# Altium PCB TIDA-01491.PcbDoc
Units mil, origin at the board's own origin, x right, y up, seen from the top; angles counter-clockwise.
Board outline 866.14 x 1043.31 mil, 4 copper layers (Top Layer, Signal Layer 1, Signal Layer 2, Bottom Layer), stack 61.2 mil thick; 63 components, 22 nets, 130 pads, 71 vias.
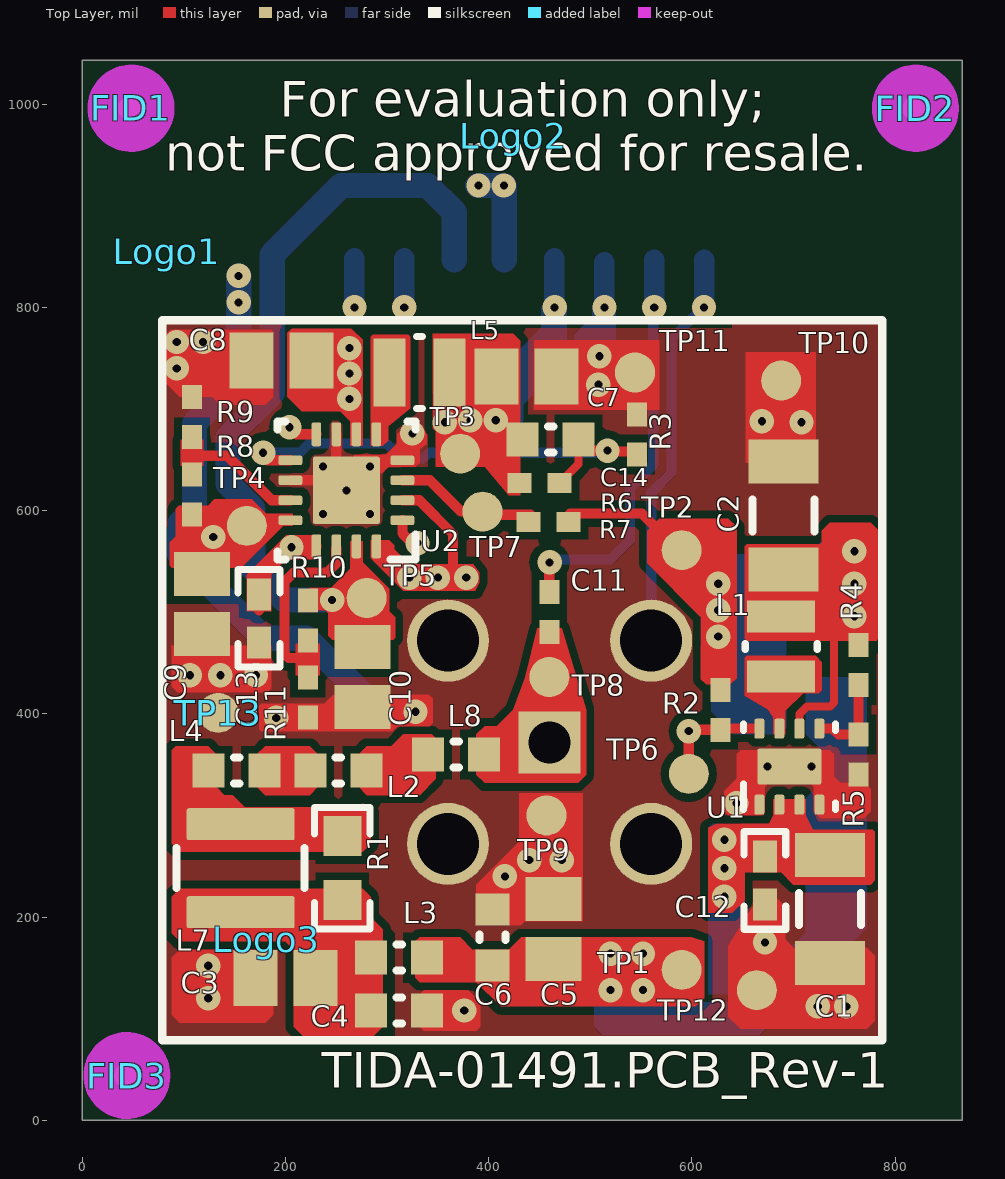
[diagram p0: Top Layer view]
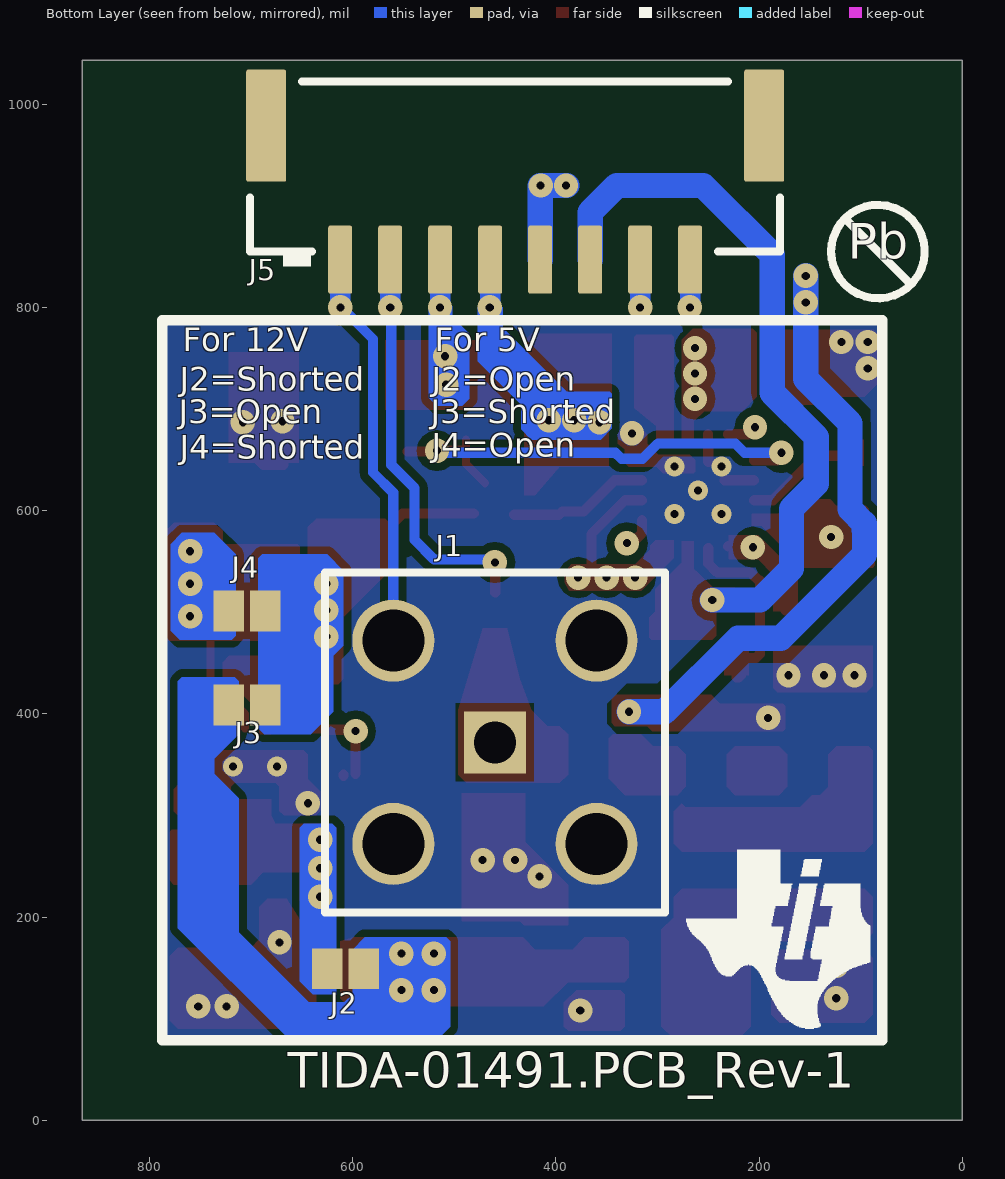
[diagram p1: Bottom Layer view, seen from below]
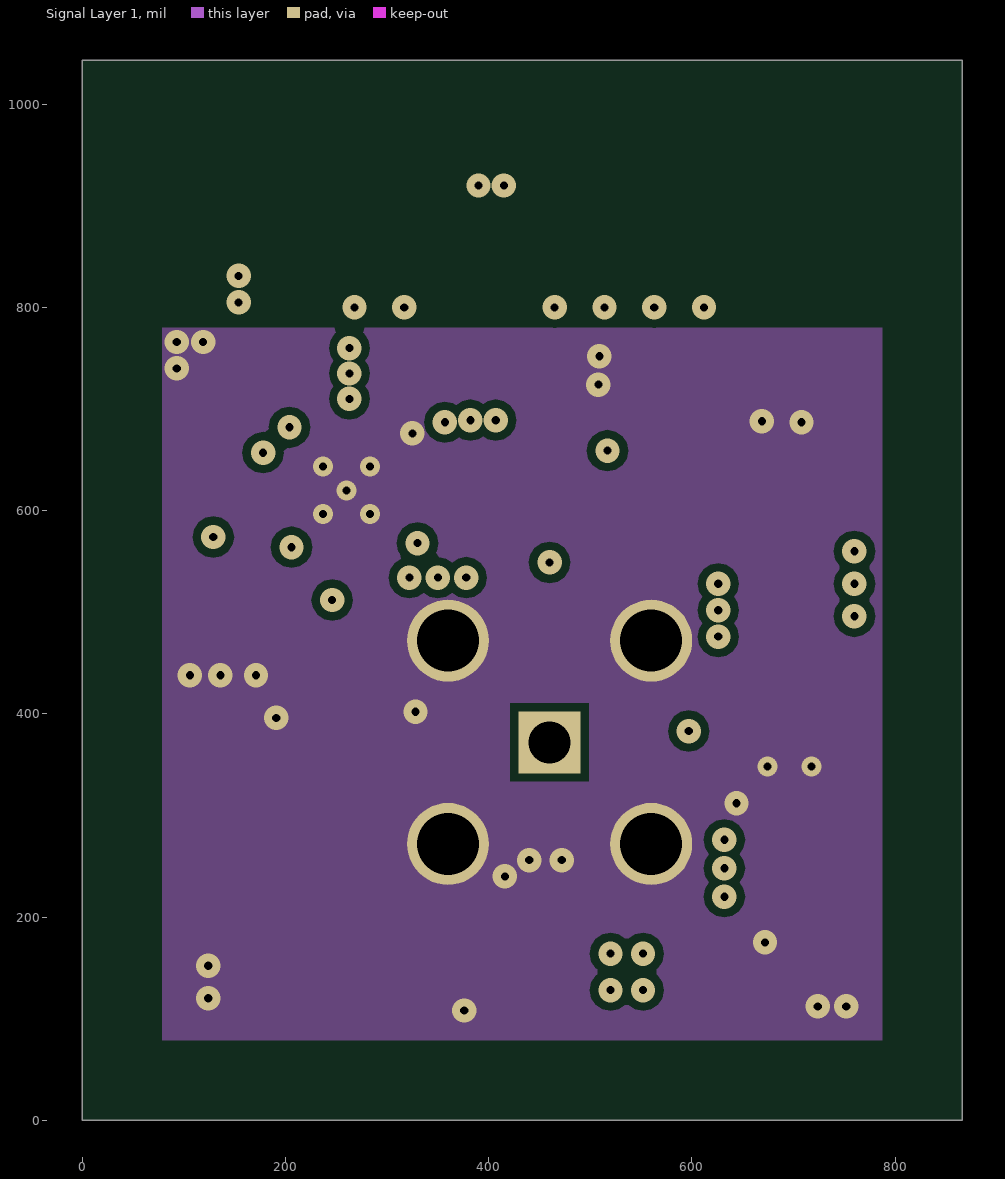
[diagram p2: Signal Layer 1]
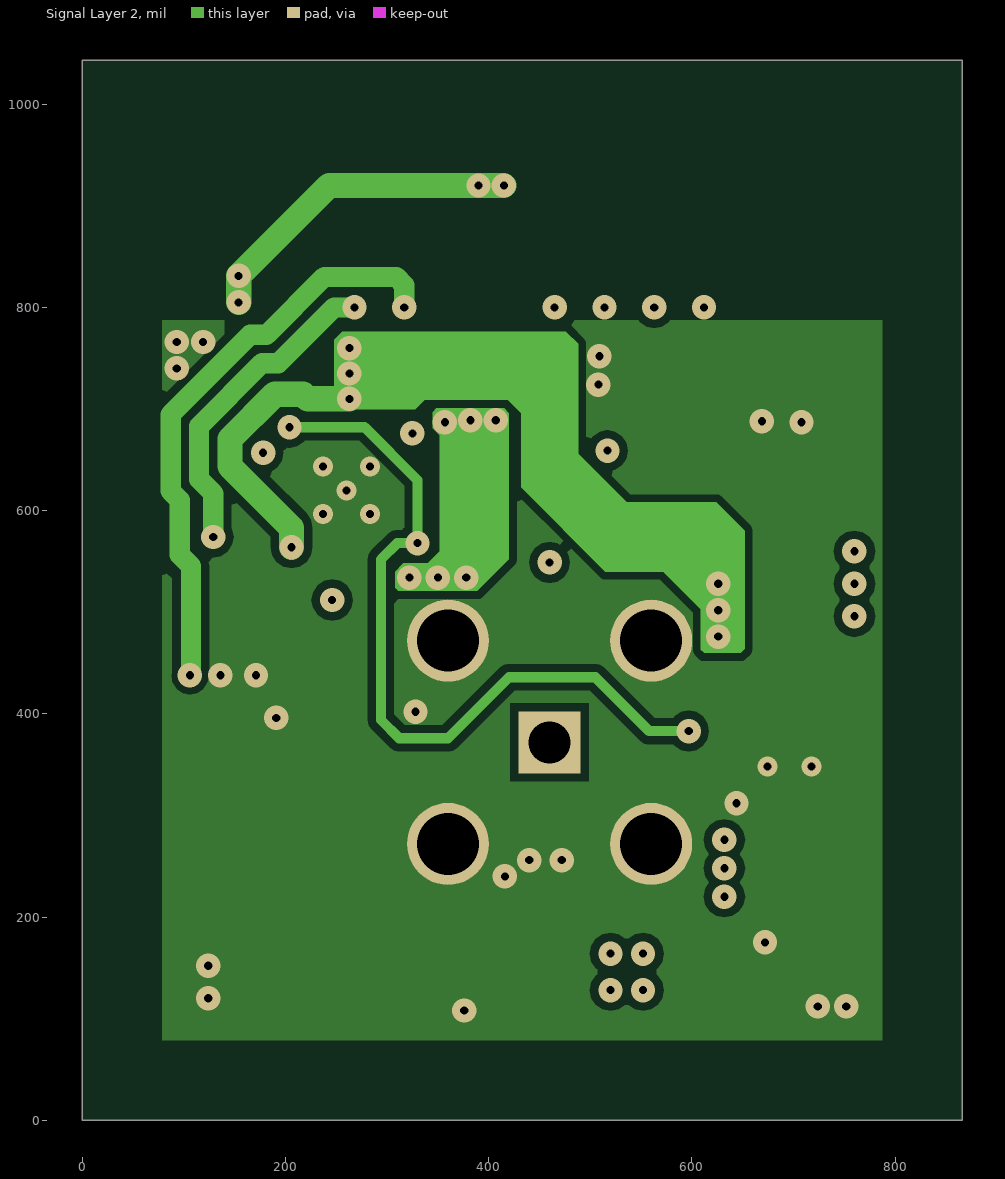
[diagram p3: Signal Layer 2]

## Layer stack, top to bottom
Top Solder: solder mask 0.4, Solder Resist, Dk 3.5
Top Layer: signal copper 1.4
Dielectric 1: prepreg 8, FR-4, Dk 4.2
Signal Layer 1: signal copper 1.4
Dielectric 2: core 8, FR-4, Dk 4.2
Signal Layer 2: signal copper 1.4
Dielectric 3: prepreg 39.6, FR-4, Dk 4.2
Bottom Layer: signal copper 1.4
Bottom Solder: solder mask 0.4, Solder Resist, Dk 3.5

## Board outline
0,0 866.14,0 866.14,1043.31 0,1043.31

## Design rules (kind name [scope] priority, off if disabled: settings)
AcuteAngle [All] p1: minimum=4.50000000000000E+0001 checktracksonly=FALSE
AssemblyTestPointUsage [All] p1: valid=2
BoardOutlineClearance BoardOutlineClearance_MountingHoles [OnCopper and InComponentClass('Mounting Holes')] p1: gap=40 ignorepadtopadclearanceinfootprint=FALSE
BoardOutlineClearance BoardOutlineClearance_Poly [OnCopper and IsPoly] p2: gap=12 ignorepadtopadclearanceinfootprint=FALSE
BoardOutlineClearance [OnCopper and Not InComponentClass('Logo') and not InComponentClass('FiducialMark') and not InRegion(1000,500,4000,800) and not InPoly] p3: gap=9 ignorepadtopadclearanceinfootprint=FALSE
Clearance Clearance_Keepouts [((IsTrack Or IsArc) And Not InPoly) And IsFree and IsKeepOut vs ((IsTrack Or IsArc) And Not InPoly) And IsFree and IsKeepOut] p1: gap=0 ignorepadtopadclearanceinfootprint=FALSE
Clearance Clearance_Poly [InPolygon] p2: gap=8 ignorepadtopadclearanceinfootprint=FALSE
Clearance [All] p3: gap=8 ignorepadtopadclearanceinfootprint=TRUE
ComponentClearance ComponentClearance_1 [InComponentClass('FiducialMark')] p1: gap=0 collisioncheckmode=3 verticalgap=10 showdistances=FALSE
ComponentClearance ComponentClearance_MountingHoles_FiducialMarks [InComponentClass('Mounting Holes') vs InComponentClass('FiducialMark')] p2: gap=0 collisioncheckmode=3 verticalgap=10 showdistances=FALSE
ComponentClearance ComponentClearance_Shunt [InComponentClass('Header') vs InComponentClass('Shunt')] p3: gap=0 collisioncheckmode=3 verticalgap=0 showdistances=FALSE
ComponentClearance ComponentClearance_Logo [InComponentClass('Logo')] p4: gap=25 collisioncheckmode=3 verticalgap=10 showdistances=FALSE
ComponentClearance ComponentClearance_ScrewToNut [(HasFootprint('NY PMS 440 0025 PH')) vs (HasFootprint('Keystone_1902C'))] p5: gap=5 collisioncheckmode=3 verticalgap=10 showdistances=FALSE
ComponentClearance ComponentClearance_MountingHoles [InComponentClass('Mounting Holes')] p6: gap=50 collisioncheckmode=3 verticalgap=100000 showdistances=FALSE
ComponentClearance ComponentClearance_SmallPassives [HasFootprint('0201*') or HasFootprint('0402*') or HasFootprint('0508') or HasFootprint('0603*') or HasFootprint('0612') or HasFootprint('0805*') or HasFootprint('0815*') or HasFootprint('0830*') or HasFootprint('1206*') or HasFootprint('1210*') or HasFootprint('1808*') or HasFootprint('1812*') or HasFootprint('1825*') or HasFootprint('2010*') or HasFootprint('2220*') or HasFootprint('2225*') or HasFootprint('2512*') or HasFootprint('2728*') or HasFootprint('3518*') vs HasFootprint('0201*') or HasFootprint('0402*') or HasFootprint('0508') or HasFootprint('0603*') or HasFootprint('0612') or HasFootprint('0805*') or HasFootprint('0815*') or HasFootprint('0830*') or HasFootprint('1206*') or HasFootprint('1210*') or HasFootprint('1808*') or HasFootprint('1812*') or HasFootprint('1825*') or HasFootprint('2010*') or HasFootprint('2220*') or HasFootprint('2225*') or HasFootprint('2512*') or HasFootprint('2728*') or HasFootprint('3518*')] p7: gap=12 collisioncheckmode=3 verticalgap=10 showdistances=FALSE
ComponentClearance ComponentClearance_THtoSMT [IsThruComponent vs IsSMTComponent] p8: gap=16 collisioncheckmode=3 verticalgap=30 showdistances=FALSE
ComponentClearance ComponentClearance_THtoTH [IsThruComponent vs IsThruComponent] p9: gap=16 collisioncheckmode=3 verticalgap=30 showdistances=FALSE
ComponentClearance [All] p10: gap=12 collisioncheckmode=3 verticalgap=10 showdistances=FALSE
DiffPairsRouting [All] p1: maxlimit=100 minlimit=10 mostfreqgap=10 toplayer_minwidth=15 toplayer_maxwidth=15 toplayer_prefwidth=15 midlayer1_minwidth=15 midlayer1_maxwidth=15 midlayer1_prefwidth=15 midlayer2_minwidth=15 midlayer2_maxwidth=15 midlayer2_prefwidth=15 bottomlayer_minwidth=15 bottomlayer_maxwidth=15 bottomlayer_prefwidth=15 maxuncoupledlength=1000
FabricationTestPointUsage TestPointUsage [All] p1: valid=2 allowmultiple=FALSE
FabricationTestpoint Testpoint [All] p1: side=3 testpointundercomponent=TRUE minsize=40 maxsize=100 preferedsize=60 minholesize=0 maxholesize=40 preferedholesize=32 testpointgrid=1 allowsidetop=TRUE allowsidebottom=TRUE usegrid=TRUE gridtolerance=0.01
FanoutControl Fanout_LCC [IsLCC] p1: bgadir=Out bgaviamode=Centered fanoutstyle=Auto fanoutdirection=Alternating viagrid=1 // Fanout_LCC (Default Rule)
FanoutControl Fanout_BGA [IsBGA] p2: bgadir=Out bgaviamode=Centered fanoutstyle=Auto fanoutdirection=Alternating viagrid=1 // Fanout_BGA (Default Rule)
FanoutControl Fanout_Default [All] p4: bgadir=Out bgaviamode=Centered fanoutstyle=Auto fanoutdirection=Alternating viagrid=1 // Fanout_Default (Default Rule)
FanoutControl Fanout_Small [(CompPinCount < 5)] p5: bgadir=Out bgaviamode=Centered fanoutstyle=Auto fanoutdirection=OutThenIn viagrid=1 // Fanout_Small (Default Rule)
HoleSize [All] p1: absolutevalues=TRUE maxlimit=251 minlimit=7.87 maxpercent=80.000 minpercent=20.000
MinimumAnnularRing MinimumAnnularRing_ThermalPadVias [IsVia and InAnyComponent] p1: minimumring=5.91
MinimumAnnularRing [All] p2: minimumring=8
MinimumSolderMaskSliver MinimumSolderMaskSliver_Logo [InComponentClass('Logo') vs InComponentClass('Logo')] p1: minsoldermaskwidth=0.7
MinimumSolderMaskSliver [All] p2: minsoldermaskwidth=3
PlaneClearance [All] p1: clearance=8
PlaneConnect [All] p1: planeconnectstyle=Direct reliefexpansion=10 reliefentries=4 reliefconductorwidth=10 reliefairgap=10
PolygonConnect [All] p1: connectstyle=Direct reliefconductorwidth=10 reliefentries=4 polygonreliefangle="90 Angle" airgapwidth=10
RoutingVias ThermalPadVias [IsVia and InAnyComponent] p1: holewidth=8 width=24 viastyle="Through Hole" minholewidth=6 minwidth=16 maxholewidth=18 maxwidth=30
RoutingVias [All] p2: holewidth=8 width=16 viastyle="Through Hole" minholewidth=5 minwidth=10 maxholewidth=12 maxwidth=30
SilkToBoardRegionClearance [Not ((IsComment or IsDesignator) And (Hide <> 'False')) and not InRegion(1000,500,4000,800)] p1:
SilkToSilkClearance SilkToSilkClearance_Pb-FreeLogo [(HasFootprint('Pb-Free_Overlay_Medium') OR HasFootprint('Pb-Free_Overlay_Small')) vs (HasFootprint('Pb-Free_Overlay_Medium') OR HasFootprint('Pb-Free_Overlay_Small'))] p1: silktosilkclearance=0
SilkToSilkClearance [All] p2: silktosilkclearance=1
SilkToSolderMaskClearance SilkToComponentPadClearance [(IsPad or IsFill or IsRegion) and InAnycomponent] p1: minsilkscreentomaskgap=1 clearancetoexposedcopper=TRUE
SilkToSolderMaskClearance "Silk to Solder Mask Opening" [All] p2: minsilkscreentomaskgap=4 clearancetoexposedcopper=FALSE
SolderMaskExpansion [All] p1: expansion=1.97
Width [All] p1: maxlimit=100 minlimit=6 preferedwidth=8 checkconnectedcopper=TRUE
14 further rules are at their usual default settings.

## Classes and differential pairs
component class Label: LBL1
component class AssemblyNote: ZZ1 ZZ2 ZZ3 ZZ4
component class FiducialMark: FID1 FID2 FID3
component class EVM_Hardware: FID1 FID2 FID3 LBL1 Logo1 Logo2 Logo3 ZZ1 ZZ2 ZZ3 ZZ4
component class TIDA-01491: C1 C2 C3 C4 C5 C6 C7 C8 C9 C10 C11 C12 C13 C14 J1 J2 J3 J4 J5 L1 L2 L3 L4 L5 L7 L8 R1 R2 R3 R4 R5 R6 R7 R8 R9 R10 R11 TP1 TP2 TP3 TP4 TP5 TP6 TP7 TP8 TP9 TP10 TP11 TP12 TP13 U1 U2
component class Logo: Logo3

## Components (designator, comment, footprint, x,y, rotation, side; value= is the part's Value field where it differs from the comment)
C1 "GCM31CC71E106KA03L" 1206_190L 736,208 r270 top value=10uF
C2 "GCM31CR70J226KE23L" 1206_180L 690,595.15 r90 top value=22uF
C3 "GCM21BC71E475KE36L" 0805L 200,140 r180 top value=4.7uF
C4 "CGA3E2X7R1E104K080AA" 0603L 312,108 r0 top value=0.1uF
C5 "GCM21BC71E475KE36L" 0805L 464,188 r90 top value=4.7uF
C6 "CGA3E2X7R1E104K080AA" 0603L 404,180 r90 top value=0.1uF
C7 "GCM21BR70J106KE22L" 0805L 437.53,732 r0 top value=10uF
C8 "GCM21BR70J106KE22L" 0805L 196,748 r180 top value=10uF
C9 "GCM21BR70J106KE22L" 0805L 118,508 r270 top value=10uF
C10 "GCM21BR70J106KE22L" 0805L 276,436 r270 top value=10uF
C11 "CGA2B1X7R1E333K050BC" 0402L 459.68,500.01 r270 top value=0.033uF
C12 "CGA2B3X7R1H103K050BB" 0402 672,236 r270 top value=0.01uF
C13 "CGA2B3X7R1H103K050BB" 0402 174,494 r270 top value=0.01uF
C14 "GCM1885C1H680JA16D" 0603L 461,670 r0 top value=68pF
FID1 "Fiducial" Fiducial6.4-20 48,996 r0 top
FID2 "Fiducial" Fiducial6.4-20 820,996 r0 top
FID3 "Fiducial" Fiducial6.4-20 44,44 r0 top
J1 "59S10H-40ML5-Z" Rosenberger_59S10H-40ML5-Z 460,372 r270 bottom
J2 "JMP-36-30X40SMT" JMP-36-30X40SMT 607,149 r0 bottom
J3 "JMP-36-30X40SMT" JMP-36-30X40SMT 704,408.69 r180 bottom
J4 "JMP-36-30X40SMT" JMP-36-30X40SMT 704,501.26 r0 bottom
J5 "BM08B-GHS-TBT(LF)(SN)(N)" JST_BM08B-GHS-TBT 439.97,938.54 r180 bottom
L1 "SRN2010TA-2R2M" SRN2010TA 688,466.26 r90 top value=2.2uH
L2 "BLM18HE152SN1D" 0603L 252,344 r180 top value="1500 ohm"
L3 "BLM18KG601SN1D" 0603L 312,160 r0 top value="600 ohm"
L4 "BLM18HE152SN1D" 0603L 152,344 r180 top value="1500 ohm"
L5 "SRN2010TA-2R2M" SRN2010TA 332,736 r0 top value=2.2uH
L7 "LQH3NPZ100MJRL" LQH3NPZ_JR 156,248 r270 top value=10uH
L8 "BLM18HE152SN1D" 0603L 368,360 r180 top value="1500 ohm"
LBL1 "Size: 0.65\" x 0.20 \"" Label_650x200 976,2173 r0 top
Logo1 "Pb-Free Symbol" Pb-Free_Overlay_Small 83,855 r180 top
Logo2 "FCC disclaimer" FCC_disclaimer_stacked 424,969 r0 top
Logo3 "Texas Instruments" TI_Symbol_Overlay_Small 181,178 r180 top
R1 "ERA-3AEB4121V" 0603 256,248 r270 top value=4.12k
R2 "CRCW040211K0JNED" 0402L 628,404 r90 top value=11k
R3 "ERJ-2RKF1503X" 0402L 546,675 r270 top value=150k
R4 "ERJ-2RKF4703X" 0402L 764,448 r90 top value=470k
R5 "ERJ-2RKF1503X" 0402L 764,360 r90 top value=150k
R6 "CRCW0402300KFKED" 0402L 450,627 r180 top value=300k
R7 "ERJ-2RKF4703X" 0402L 459,589 r0 top value=470k
R8 "ERJ-2RKF6983X" 0402L 108,616 r270 top value=698k
R9 "ERJ-2RKF1503X" 0402L 108,692 r270 top value=150k
R10 "ERJ-2RKF2103X" 0402L 222,492 r90 top value=210k
R11 "ERJ-2RKF1503X" 0402L 222,416 r90 top value=150k
TP1 "TP_SM_1MM" TP_SM_1MM 590,148 r180 top
TP2 "TP_SM_1MM" TP_SM_1MM 590,561 r270 top
TP3 "TP_SM_1MM" TP_SM_1MM 372,656 r0 top
TP4 "TP_SM_1MM" TP_SM_1MM 162,585 r0 top
TP5 "TP_SM_1MM" TP_SM_1MM 280,514 r0 top
TP6 "TP_SM_1MM" TP_SM_1MM 597,341 r90 top
TP7 "TP_SM_1MM" TP_SM_1MM 394,599 r90 top
TP8 "TP_SM_1MM" TP_SM_1MM 459.68,436.24 r90 top
TP9 "TP_SM_1MM" TP_SM_1MM 457,300 r90 top
TP10 "TP_SM_1MM" TP_SM_1MM 688,728 r90 top
TP11 "TP_SM_1MM" TP_SM_1MM 544,736 r90 top
TP12 "TP_SM_1MM" TP_SM_1MM 664,128 r90 top
TP13 "TP_SM_1MM" TP_SM_1MM 134,401 r90 top
U1 "TPS62160QDSGRQ1" DSG0008A 696,348 r90 top
U2 "TPS65000TRTERQ1" RTE0016C 260,620 r180 top
ZZ1 "This Assembly Note is for PCB labels only" AssemblyNoteLabel 185,3938 r0 top
ZZ2 "This Assembly Note will show in the PcbDoc and associated outputs" AssemblyNote 185,3829.11 r0 top
ZZ3 "This Assembly Note will show in the PcbDoc and associated outputs" AssemblyNote 185,3740.56 r0 top
ZZ4 "This Assembly Note will show in the PcbDoc and associated outputs" AssemblyNote 185,3652 r0 top

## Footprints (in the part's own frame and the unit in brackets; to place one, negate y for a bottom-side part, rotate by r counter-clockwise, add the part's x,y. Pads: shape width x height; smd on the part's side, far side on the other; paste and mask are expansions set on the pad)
0402 [mm] "0402 from SM-752 data"
  rect 0.8x0.6 smd: 1(-0.6,0) 2(0.6,0)
  silkscreen extent -1.22,-0.52 1.22,0.52, body extent -0.55,-0.3 0.55,0.3, height 0.6
0402L [mm] "0402 from SM-752 data"
  rect 0.6x0.5 smd: 1(-0.5,0) 2(0.5,0)
  body extent -0.55,-0.3 0.55,0.3, height 0.6
0603 [mm] "0603 from SM-752 data"
  rect 1x0.95 smd: 1(-0.8,0) 2(0.8,0)
  silkscreen extent -1.52,-0.69 1.52,0.69, body extent -0.87,-0.47 0.87,0.47, height 1
0603L [mm] "0603 from SM-752 data"
  rect 0.8x0.85 smd: 1(-0.7,0) 2(0.7,0)
  silkscreen extent -0.07,-0.33 0.07,0.33, body extent -0.87,-0.47 0.87,0.47, height 1
0805L [mm] "0805 from SM-752 data"
  rect 1.1x1.4 smd: 1(-0.75,0) 2(0.75,0)
  body extent -1.1,-0.72 1.1,0.72, height 1.45
1206_180L [mm] "1206_180"
  rect 1.1x1.75 smd: 1(-1.35,0) 2(1.35,0)
  silkscreen extent -0.4,-0.77 0.4,0.77, body extent -1.75,-0.95 1.75,0.95, height 1.8
1206_190L [mm] "1206_190"
  rect 1.1x1.75 smd: 1(-1.35,0) 2(1.35,0)
  silkscreen extent -0.4,-0.77 0.4,0.77, body extent -1.75,-0.95 1.75,0.95, height 1.9
AssemblyNote [mil] "Assembly Note"
AssemblyNoteLabel [mil] "Assembly Note for PCB Labels"
DSG0008A [mm] "SON, 8-Leads, Body 2x2mm, Pitch 0.5mm, Thermal Pad 1.6x0.9mm, TI Recommended"
  rrect40% 0.5x0.25 smd: 1(-0.95,0.75) 2(-0.95,0.25) 3(-0.95,-0.25) 4(-0.95,-0.75) 5(0.95,-0.75) 6(0.95,-0.25) 7(0.95,0.25) 8(0.95,0.75)
  rrect14% 0.9x0.7 on Top Paste: 9(0,0.45) 9(0,-0.45)
  rrect11% 0.9x1.6 smd paste-0.45: 9(0,0)
  silkscreen extent -1.07,-1.15 1.07,1.15, body extent -1,-1 1,1, height 0.77
FCC_disclaimer_stacked [mil]
Fiducial6.4-20 [mil]
  round 25 smd mask+26.87: 1(0,0)
  Top Layer keep-out circle w46.37: c0,0 r19.68
JMP-36-30X40SMT [mil] "from PADS library"
  rect 30x40 smd mask+3: 1(-18,0) 2(18,0)
JST_BM08B-GHS-TBT [mm] "Header(shrouded), 1.25mm, 8x1, TH"
  rrect17% 0.6x1.7 smd: 1(-4.375,-2.325) 2(-3.125,-2.325) 3(-1.875,-2.325) 4(-0.625,-2.325) 5(0.625,-2.325) 6(1.875,-2.325) 7(3.125,-2.325) 8(4.375,-2.325)
  rrect10% 1x2.8 smd: MP1(-6.225,1.025) MP2(6.225,1.025)
  silkscreen extent -6.63,-2.5 6.63,2.12, body extent -6.63,-2.83 6.62,2.12, height 4.2
Label_650x200 [mil] "Thermal Transfer Label"
  silkscreen extent -325,-100 325,100, body extent -325,-100 325,100, height 1
LQH3NPZ_JR [mm] "SMD, 2-Leads, Body 3x3mm"
  rrect12% 0.8x2.7 smd: 1(-1.1,0) 2(1.1,0)
  silkscreen extent -0.5,-1.6 0.5,1.6, body extent -1.6,-1.6 1.6,1.6, height 1.2
Pb-Free_Overlay_Small [mil]
Rosenberger_59S10H-40ML5-Z [mm] "Connector, HF, TH"
  rect 1.55x1.55 hole 1.05: 1(0,0)
  round 2.05 hole 1.55: 2(-2.54,2.54) 3(2.54,2.54) 4(2.54,-2.54) 5(-2.54,-2.54)
  silkscreen extent -4.25,-4.25 4.25,4.25, body extent -4.25,-5.75 4.25,4.25, height 12.45
RTE0016C [mm] "Texas Insturments"
  rrect42% 0.6x0.24 smd: 1(-1.4,0.75) 2(-1.4,0.25) 3(-1.4,-0.25) 4(-1.4,-0.75) 9(1.4,-0.75) 10(1.4,-0.25) 11(1.4,0.25) 12(1.4,0.75)
  rrect42% 0.24x0.6 smd: 5(-0.75,-1.4) 6(-0.25,-1.4) 7(0.25,-1.4) 8(0.75,-1.4) 13(0.75,1.4) 14(0.25,1.4) 15(-0.25,1.4) 16(-0.75,1.4)
  rrect6% 1.55x1.55 on Top Paste: 17(0,0)
  rrect6% 1.68x1.68 smd paste-0.85: 17(0,0)
  silkscreen extent -1.72,-1.73 1.72,1.73, body extent -1.57,-1.57 1.58,1.58, height 0.81
SRN2010TA [mm] "SMD, 2-Leads, Body 2.0x1.6mm"
  rect 0.8x1.7 smd: 1(-0.75,0) 2(0.75,0)
  silkscreen extent -0.08,-0.9 0.08,0.9, body extent -1,-0.8 1,0.8, height 0.95
TI_Symbol_Overlay_Small [mil]
TP_SM_1MM [mm] "1mm Test Point, SMT"
  round 1 smd paste-0.5: 1(0,0)

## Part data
C1: library part CMP-0008807-2, "CAP, CERM, 10 uF, 25 V, +/- 10%, X7S, AEC-Q200 Grade 1, 1206_190", Cap_Case=1206, Manufacturer=MuRata, Supplier Part Number 1=490-12661-1-ND, TempCo=X7S, Tolerance_%=10%, Value1=Unknown, Value2=25V, ValueDisplayed=10uF
C2: "CAP, CERM, 22 µF, 6.3 V,+/- 10%, X7R, AEC-Q200 Grade 1, 1206", Cap_Case=1206, Manufacturer=MuRata, Supplier Part Number 1=490-4843-1-ND, TempCo=X7R, Tolerance_%=10, Value2=6.3V, ValueDisplayed=22µF
C3 C5: "CAP, CERM, 4.7 µF, 25 V,+/- 10%, X7S, AEC-Q200 Grade 1, 0805", Cap_Case=0805, Manufacturer=MuRata, Supplier Part Number 1=81-GCM21BC71E475KE6L, TempCo=X7S, Tolerance_%=10, Value2=25V, ValueDisplayed=4.7µF
C4 C6: "CAP, CERM, 0.1 µF, 25 V,+/- 10%, X7R, AEC-Q200 Grade 1, 0603", Cap_Case=0603, Manufacturer=TDK, Supplier Part Number 1=445-5667-1-ND, TempCo=X7R, Tolerance_%=10, Value2=25V, ValueDisplayed=0.1µF
C7 C8 C9 C10: "CAP, CERM, 10 µF, 6.3 V,+/- 10%, X7R, AEC-Q200 Grade 1, 0805", Cap_Case=0805, Manufacturer=MuRata, Supplier Part Number 1=490-5319-1-ND, TempCo=X7R, Tolerance_%=10, Value2=6.3V, ValueDisplayed=10µF
C11: library part CMP-0006306-2, "CAP, CERM, 0.033 uF, 25 V, +/- 10%, X7R, AEC-Q200 Grade 1, 0402", Cap_Case=0402, Manufacturer=TDK, Supplier Part Number 1=445-12247-1-ND, TempCo=X7R, Tolerance_%=10%, Value1=Unknown, Value2=25V, ValueDisplayed=0.033uF
C12 C13: library part CMP-0006324-2, "CAP, CERM, 0.01 uF, 50 V, +/- 10%, X7R, AEC-Q200 Grade 1, 0402", Cap_Case=0402, Manufacturer=TDK, Supplier Part Number 1=445-6893-1-ND, TempCo=X7R, Tolerance_%=10%, Value1="0.333065 ohm", Value2=50V, ValueDisplayed=0.01uF
C14: library part CMP-0007129-4, "CAP, CERM, 68 pF, 50 V, +/- 5%, C0G/NP0, AEC-Q200 Grade 1, 0603", Cap_Case=0603, Manufacturer=MuRata, Supplier Part Number 1=490-4961-1-ND, TempCo=C0G/NP0, Tolerance_%=5%, Value1=Unknown, Value2=50V, ValueDisplayed=68pF
FID1 FID2 FID3: "Fiducial mark.  There is nothing to buy or mount.", Manufacturer=N/A
J1: library part CMP-0075127-1, "Connector, HF, 50 Ohm, TH", Color=Waterblue, Manufacturer=Rosenberger
J2 J3 J4: library part CMP-0003883-1, "Jumper, SMT", Manufacturer=Any
J5: library part CMP-0078455-1, "Header(shrouded), 1.25mm, 8x1, Tin, TH", Color=Natural, Current_A=1A, Manufacturer="JST Manufacturing", Supplier Part Number 1=455-1584-1-ND, Voltage_V=50V
L1 L5: library part CMP-0056730-1, "Inductor, Shielded, Ferrite, 2.2 uH, 1.2 A, 0.174 ohm, AEC-Q200 Grade 1, SMD", Manufacturer=Bourns, Supplier Part Number 1=SRN2010TA-2R2MCT-ND, Value1="0.174 ohm", Value2=1.2A, ValueDisplayed=2.2uH
L2 L4 L8: "Ferrite Bead, 1500 ohm @ 100 MHz, 0.5 A, 0603", Manufacturer=MuRata, Supplier Part Number 1=490-5216-1-ND, Value1="0.5 ohm", Value2=0.5A, ValueDisplayed="1500 ohm"
L3: "Ferrite Bead, 600 ohm @ 100 MHz, 1.3 A, 0603", Manufacturer=MuRata, Supplier Part Number 1=490-5258-1-ND, Value1="0.15 ohm", Value2=1.3A, ValueDisplayed="600 ohm"
L7: library part CMP-0058702-1, "Inductor, Wirewound, Ferrite, 10 uH, 0.81 A, 0.288 ohm, AEC-Q200 Grade 1, SMD", Manufacturer=MuRata, Supplier Part Number 1=81-LQH3NPZ100MJRL, Value1="0.288 ohm", Value2=0.81A, ValueDisplayed=10uH
LBL1: library part THT-14-423-10, "Thermal Transfer Printable Labels, 0.650\" W x 0.200\" H - 10,000 per roll", Manufacturer=Brady, Supplier Part Number 1=97C5133
Logo1: library part Pb-Free
Logo2: library part FCC_disclaimer, "FCC_disclaimer"
Logo3: library part TI_Logo, "Texas Instrument Corporate Signature"
R1: library part CMP-0023378-3, "RES, 4.12 k, 0.1%, 0.1 W, AEC-Q200 Grade 0, 0603", Manufacturer=Panasonic, Power_W=100mW, Supplier Part Number 1=P4.12KDBCT-ND, TempCo="25 ppm/C", Tolerance_%=0.1%, Value2=0.1W, Value_Code=4k12, ValueDisplayed=4.12k
R2: library part CMP-0026830-3, "RES, 11 k, 5%, 0.063 W, AEC-Q200 Grade 0, 0402", Manufacturer=Vishay-Dale, Power_W=63mW, Supplier Part Number 1=541-11KJCT-ND, TempCo="200 ppm/C", Tolerance_%=5%, Value2=0.063W, Value_Code=11k0, ValueDisplayed=11k
R3 R5 R9 R11: library part CMP-0026669-1, "RES, 150 k, 1%, 0.1 W, AEC-Q200 Grade 0, 0402", Manufacturer=Panasonic, Power_W=100mW, Supplier Part Number 1=P150KLCT-ND, TempCo="100 ppm/C", Tolerance_%=1%, Value2=0.1W, Value_Code=150k
R4 R7: library part CMP-0078374-1, "RES, 470 k, 1%, .1 W, AEC-Q200 Grade 0, 0402", Manufacturer=Panasonic, Power_W=0.1, Supplier Part Number 1=P470KLCT-ND, TempCo="100 ppm/C", Tolerance_%=1, Value1=1%, Value2=.1W, Value_Code=470k
R6: "RES, 300 k, 1%, 0.063 W, AEC-Q200 Grade 0, 0402", Manufacturer=Vishay-Dale, Power_W=0.063, Supplier Part Number 1=541-300KLCT-ND, TempCo="100 ppm/C", Tolerance_%=1, Value1=1%, Value2=0.063W, Value_Code=300k
R8: library part CMP-0078375-1, "RES, 698 k, 1%, .1 W, AEC-Q200 Grade 0, 0402", Manufacturer=Panasonic, Power_W=0.1, Supplier Part Number 1=P698KLCT-ND, TempCo="100 ppm/C", Tolerance_%=1, Value1=1%, Value2=.1W, Value_Code=698k
R10: library part CMP-0026678-1, "RES, 210 k, 1%, 0.1 W, AEC-Q200 Grade 0, 0402", Manufacturer=Panasonic, Power_W=100mW, Supplier Part Number 1=P210KLCT-ND, TempCo="100 ppm/C", Tolerance_%=1%, Value2=0.1W, Value_Code=210k
TP1 TP2 TP3 TP4 TP5 TP6 TP7 TP8 TP9 TP10 TP11 TP12 TP13: library part CMP-0003825-1, "1mm Test Point, SMT", Manufacturer=Any
U1: "3V-17V 1A Automotive Step-Down Converters in 2x2SON, DSG0008A (WSON-8)", Alternate Manufacturer="Texas Instruments", Alternate PartNumber=TPS62160QDSGTQ1
U2: "2.25MHz Step-Down Converter with Dual LDOs & SVS Power Management IC (PMIC), RTE0016C (WQFN-16)", Alternate Manufacturer="Texas Instruments"
ZZ1: library part AssemblyNoteLabel
ZZ2 ZZ3 ZZ4: library part AssemblyNote

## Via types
v1: diameter 24, hole 8, Top Layer to Bottom Layer, tented both sides, 64 vias
v2: diameter 19.68, hole 7.87, Top Layer to Bottom Layer, 7 vias

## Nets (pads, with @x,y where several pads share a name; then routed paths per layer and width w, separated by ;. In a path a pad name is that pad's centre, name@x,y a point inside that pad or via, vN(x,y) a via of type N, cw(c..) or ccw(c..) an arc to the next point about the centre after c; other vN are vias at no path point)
+1V2: C10.1 J5.6 R10.2 TP5.1 U2.15 | length 693
  Bottom Layer w25: v1(246,512) 199,512 168,543 168,602 143.5,626.5 143.5,672.46 187,715.96 187,852 255,920 340,920 366.15,893.85 J5.6
+1V8: C7.1 C14.1 J5.4 L5.2 R6.2 TP3.1 U2.2 U2.16 | length 149.1
  Top Layer w10: U2.2 331.84,610.16 365,577 365,540
  Bottom Layer w20: v1@464.61,800 J5.4@464.61,848.46
  other v1: 322,534 350,534 378,534 357,687 382,689 407,689 465,800
+2V8: C9.1 J5.8 R8.2 TP4.1 U2.12 | length 364.5
  Signal Layer 2 w20: v1(129,574) 129,616.87 115,630.87 115,683.1 176.9,745 193,745 248,800 v1(268,800)
  Bottom Layer w20: v1@267.76,800.24 J5.8@267.76,848.46
+VCC_PMIC_3V3: C8.1 C13.1 J3.2 J4.1 R2.2 R7.2 TP2.1 U2.6 U2.13 | length 466.2
  Top Layer w10: C13.1@174,502 C13.1 174,536 202.88,564.88 U2.13 ; R7.2@480.37,597 551,597 568,580
  Signal Layer 2 w25: v1(206,564) 206,583 145.5,643.5 145.5,670.46 189.54,714.5 217.46,714.5 221.96,710 v1(263,710)
  other v1: 626,476 626,502 626,528 263,735 263,760
+VCC_POC: C5.1 C6.1 J2.1 J3.1 L3.2 TP1.1
  other v1: 520,128 552,128 520,164 552,164
DATA: C11.1 J5.2 | length 404.6
  Top Layer w10: C11.1 v1@459.68,548.68
  Bottom Layer w10: v1(460,549) 463,552 520,552 539,571 539,622 562,645 v1@562,802
  Bottom Layer w20: v1(563,800) J5.2
DCDC_SW: L5.1 U2.5
FB: R4.1 R5.2 U1.5 | length 89.5
  Top Layer w10: U1.5 738.6,385.4 744.31,379.69 R5.2 R4.1
FB_DCDC: C14.2 R3.2 R6.1 U2.9 | length 491.4
  Top Layer w8: R6.1 488.56,645.87 488.56,659 C14.2
  Top Layer w10: v1(178,657) 182.47,649.53 U2.9 ; C14.2@488.56,659 v1(517,659) ; v1@517.31,658.31 R3.2@546,658.31
  Bottom Layer w10: v1(178,657) 214.36,657 223.43,666.07 299.57,666.07 314.64,651 335.36,651 341.36,657 515,657 v1(517,659)
FB_LDO1: R8.1 R9.2 U2.11 | length 148.4
  Top Layer w10: R8.1 108,654 ; R9.2@108,669 108,654 ; U2.11 186.49,610.16 142.64,654 108,654
FB_LDO2: R10.1 R11.2 U2.14 | length 210.3
  Top Layer w10: 199,531 199,459 203,455 222,455 ; 200,531 207,538 ; 208,539 241,539 250,548 U2.14@250,563 ; R11.2@217.69,438 R11.2@220,435.69 ; R11.2 222,455 ; R10.1@223,475 222,474 R10.1 222,455
GND: C1.2 C2.2 C3.2 C4.2 C5.2 C6.2 C7.2 C8.2 C9.2 C10.2 C12.2 C13.2 J1.2 J1.3 J1.4 J1.5 J5.1 J5.3 J5.5 J5.7 R3.1 R5.1 R9.1 R11.1 TP9.1 TP10.1 TP11.1 TP12.1 TP13.1 U1.1 U1.4 U1.9@696,348 U2.4 U2.7 U2.10 U2.17@260,620 | length 2348.9
  Top Layer w10: U2.10 233.84,629.84 U2.17@234,630 ; U2.17@250,648 U2.7 ; v1(644,312) 642.8,312 641.4,310.6 U1.1 ; v1@668.15,684.85 668.15,645.15 688,645.15 708,665.15 v1@708,685 ; U1.4 754.6,310.6 764,320 R5.1 R5.1@764,344
  Signal Layer 2 w20: v1@106,437 v1(106,438) 107,439 107,545.57 95.98,556.6 95.98,610.29 87,619.27 87,694.69 165.31,773 181.4,773 238.4,830 309,830 317,822 v1(317,800)
  Signal Layer 2 w25: v1(154,805) v1(154,831) 243,920 v1(390,920) v1(415,920)
  Bottom Layer w10: J1.2 J1.2@364,472 ; J1.5 560,617.55 580,637.54 580,769 v1@612,801
  Bottom Layer w20: v1@316.97,800.97 J5.7@316.97,848.46 ; v1@513.82,797.82 J5.3@513.82,844.46 ; v1(612,800) 612.21,800.21 J5.1
  Bottom Layer w25: v1(154,831) v1(154,805) 154,729.63 110.5,686.13 110.5,601.46 96.5,587.46 96.5,580.88 96.19,580.57 96.19,556.81 178.72,474.28 220.72,474.28 293,402 v1(328,402) ; v1@389.33,920 v1(390,920) v1(415,920) 415.36,919.64 J5.5
  other v1: 376,108 724,112 752,112 124,120 124,152 672,175 416,240 440,256 472,256 191,396 136,438 171,438 325,676 708,687 669,688 508,724 93,740 509,752 93,766 119,766 514,800
  other v2: 674.35,348 717.65,348 236.77,596.77 283.23,596.77 260,620 236.77,643.23 283.23,643.23
NetC1_1: C1.1 C12.1 J2.2 U1.2 U1.3
  other v1: 632,220 632,248 632,276
NetC2_1: C2.1 J4.2 L1.2 R4.2 U1.6 | length 120.2
  Top Layer w8: U1.6 705.84,399.84 713.24,407.24 736.24,407.24 740,411 740,478
  other v1: 760,496 760,528 760,560
NetC3_1: C3.1 C4.1 L3.1 L7.2 R1.2
NetC11_2: C11.2 J1.1 L8.1 TP8.1
NetL2_1: L2.1 L8.2
NetL2_2: L2.2 L4.1
NetL4_2: L4.2 L7.1 R1.1
PG: R7.1 TP7.1 U2.3 | length 139.9
  Top Layer w10: U2.3 342.16,629.84 373,599 TP7.1 397,596 R7.1@441,596
PRE_PG: R2.1 TP6.1 U1.8 U2.1 U2.8 | length 941.4
  Top Layer w10: v1@205,681 210.88,675.12 U2.8 ; U2.1 315.12,577.88 324,569 v1@332,569 ; TP6.1 v1(597,383) ; v1@597,384.32 R2.1 629.09,385.4 U1.8 ; TP6.1@609,339 TP6.1@609,340
  Signal Layer 2 w10: v1(204,682) 278,682 330,630 v1(330,568) 310,568 294,552 294,394 312,376 360,376 420,436 505,436 558,383 v1(597,383)
SW: L1.1 U1.7
pads on no net: FID1.1 FID2.1 FID3.1 J5.MP1 J5.MP2 U1.9@678.28,348 U1.9@713.72,348 U2.17@260,620

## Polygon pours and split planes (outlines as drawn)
GND on Top Layer "Top Layer-No Net" (solid, remove dead copper, pour order 62): 78.74,787.4 78.74,78.74 787.4,78.74 787.4,787.4
GND on Signal Layer 1 "Signal Layer 1-No Net" (solid, remove dead copper, pour order 60): 78.74,78.74 787.4,78.74 787.4,780 78.74,780
GND on Signal Layer 2 "Signal Layer 2-No Net" (solid, pour order 64): 78.74,787.4 78.74,78.74 787.4,78.74 787.4,787.4
GND on Bottom Layer "Bottom Layer-No Net" (solid, pour order 66): 78.74,787.4 78.74,78.74 787.4,78.74 787.4,787.4

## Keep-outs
Keep-Out Layer:
  text ".Layer_Name" at 577,-858.49 h60

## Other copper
Top Layer:
  rectangle net GND: 430,267 493,322
  rectangle net GND: 653,647 722,756
  rectangle net GND: 444,699 568,768
  pour cut-out: 240,824 640,824 640,780 639.5,779.5 240,779.5
  region net +1V8: 345,774 345,681 348,678 348,643 396,643 420,615.31 431,615.31 431,688 431,767 424,774
  region net +VCC_PMIC_3V3: 644,584 636,592 568,592 556,580 556,548 608,496 644,496
  region net GND: 186,467 186,465 186,425 182,421 94,421 88,427 88,467
  region net GND: 341,419 345,415 345,391 342,388 310,388 305,383 176,383 174,385 174,408 176,410 238,410 247,419
  region net +VCC_PMIC_3V3: 230,576 201,576 162,537 162,501 186,501 186,537 201,552 230,552
  region net +VCC_PMIC_3V3: 638,429 644,435 644,541 639,546 614,546 609,541 609,434 614,429
  region net FB_LDO1: 119,670 97,670 97,644 119,644
  region net +1V8: 284,571 284,553 316,521 387,521 391,529 391,539.5 385,547 322,547 307,562 307,566 302,571
  region net +2V8: 207,597 181,597 167,611 130,611 124,605 95,605 92,602 92,575 86,569 86,546 88,544 157,544 159,546 198,585 207,585
  region net +1V2: 276,570 276,549 302,523 302,501 308,495 308,475 306,473 246,473 242,477 242,499 239,502 224,502 224,524 245,524 261,540 264,543 264,570
  region net FB_LDO2: 210,469 210,438 234,438 234,469
  region net GND: 319,684 310,675 310,666 299,655 268,655 263,650 263,638 264,637 295,637 301,643 328,643 332,647 332,660.4 339,666 339,675 334,684
  region net DCDC_SW: 284,664 284,771 286,773 321,773 323,771 323,701 301,683 301,669 296,664
  region net GND: 188,776 186,778 87,778 81,772 81,727 96,712 128,712 136,704 180,704 188,712
  region net +VCC_PMIC_3V3: 276,664 276,768 265,779 206,779 202,775 202,712 216,698 254,698 264,688 264,664
  region net GND: 668,300 636,300 632,304 632,324 644,336 644,360 648,364 736,364 740,360 740,338 746,332 770,332 776,326 776,304 769,297 727,297 720,304 720,328 716,332 676,332 672,328 672,304
  region net SW: 692,380 692,403 709,420 725,420 728,423 728,451 722,457 654,457 652,455 652,418 675,404 680,396 680,380
  region net NetC2_1: 652,565 654,567 726,567 728,569 728,580 736,588 776,588 784,580 784,476 782,472 655,472 652,473.71
  region net NetC11_2: 448,484 436,436 424,404 408,388 396,388 388,380 388,340 396,332 488,332 496,340 496,404 472,484
  region net NetL2_1: 348,376 344,380 316,380 304,368 280,368 272,360 272,328 280,320 332,320 348,336
  region net NetL2_2: 232,360 224,368 180,368 172,360 172,328 180,320 224,320 232,328
  region net NetL4_2: 132,360 124,368 92,368 88,364 88,272 96,264 276,264 284,272 284,304 276,312 272,308 160,308 148,320 140,320 132,328
  region net NetC3_1: 96,228 276,228 284,220 284,200 296,188 296,92 284,80 220,80 208,92 208,168 200,176 96,176 88,184 88,220
  region net GND: 188,168 96,168 88,160 88,104 96,96 180,96 188,104
  region net GND: 388,192 388,232 430,274 492.54,274 492.54,263.46 492.54,196 435.46,196 431.46,192
  region net +VCC_POC: 328,176 332,180 372,180 384,168 420,168 432,180 600,180 612,176 612,120 604,112 412,112 388,136 332,136 328,140
  region net GND: 332,124 336,128 380,128 392,116 392,92 388,88 336,88 332,92
  region net GND: 684,218 692,210 692,178 700,170 772,170 780,162 780,98 772,90 648,90 636,102 636,171.6 665,218
  region net NetC1_1: 712,316 712,300 719,286 778,286 780,284 780,236 776,232 700,232 688,244 652,244 652,216 640,204 616,204 616,288 624,292 676,292 680,300 680,316
  text ".Layer_Name" at 577,-858.49 h60
Signal Layer 2:
  pour cut-out: 336,780 340,784 340,828 320,848 228,848 184,804 140,804 140,772.1 68,700.1 68,610.74 78.74,600 78.74,542.72 88,533.46 88,432 100,420 112,420 124,432 124,689.78 121.78,692 221.78,792 296,792 308,780
  region net +VCC_PMIC_3V3: 248,700 328,700 337,709 419,709 432,696 432,623 515,540 572,540 609,503 609,463 612,460 648,460 652,464 652,580 624,608 536,608 524,620 488,656 488,764 476,776 256,776 248,768
  region net +1V8: 348.57,700.57 345,697 345,681 352,674 352,560 340,548 316,548 308,540 308,524 311,521 389,521 420,552 420,696 415.43,700.57
Bottom Layer:
  pour cut-out: 130,800 130,740 90,700 90,610 70,590 70,550 170,450 210,450 280,380 340,380 350,390 350,410 330,430 300,430 230,500 190,500 130,560 130,670 170,710 180,710 180,800
  region net +1V8: 477,800 477,747 434,704 434,680 424,670 356,670 345,681 345,715 347,717 389,717 452,780 452,800
  region net GND: 525,801 525,711 517,703 492,703 485,710 485,774 502,791 502,801
  region net +VCC_POC: 712,380 736,356 736,341 712,317 712,185 643,116 608,116 600,124 504,124 504,92 512,84 667,84 772,189 772,346 772,432 768,436 716,436 712,432
  region net +VCC_PMIC_3V3: 693,485 647,485 619,457 619,402 641,380 687,380 693,386
  region net +VCC_PMIC_3V3: 693,477 673,457 619,457 609,467 609,541 625,557 689,557 693,553
  region net NetC2_1: 715,557 736,578 768,578 779,567 779,482 770,473 719,473 715,477
  region net +VCC_POC: 600,168 588,180 508,180 504,176 504,116 508,112 588,112 600,124
  region net NetC1_1: 616,204 616,288 620,292 648,292 652,288 652,188 652,137 639,124 616,124 616,168
  text ".Layer_Name" at 577,-858.49 h60

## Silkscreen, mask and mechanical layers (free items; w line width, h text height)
Top Overlay:
  lines w8: 78.74,78.74 78.74,787.4 787.4,787.4 787.4,78.74 78.74,78.74
  text "TIDA-01491.PCB_Rev-1" at 236,20 h60
  text ".Layer_Name" at 577,-858.49 h60
Bottom Overlay:
  lines w10: 78.74,78.74 787.4,78.74 787.4,787.4 78.74,787.4 78.74,78.74
  text "For 5V" at 519,749 h40
  text "For 12V" at 767,749 h40
  text "J2=Open" at 522,710 h40
  text "J2=Shorted" at 770,710 h40
  text "J3=Shorted" at 523,678 h40
  text "J3=Open" at 771,678 h40
  text "J4=Open" at 522,645 h40
  text "J4=Shorted" at 770,643 h40
  text "TIDA-01491.PCB_Rev-1" at 664,20 h60
  text ".Layer_Name" at 577,-858.49 h60
Top Paste:
  text ".Layer_Name" at 577,-858.49 h60
Bottom Paste:
  text ".Layer_Name" at 577,-858.49 h60
Top Solder:
  text ".Layer_Name" at 577,-858.49 h60
  text ".Layer_Name" at 577,-858.49 h60
Bottom Solder:
  text ".Layer_Name" at 577,-858.49 h60
Drill Guide:
  text ".Layer_Name" at 577,-858.49 h60
M1 Board Outline:
  the board outline again, w10
  text ".Layer_Name" at 577,-858.49 h60
M2 Board Dimensions:
  rectangle: 125,-400 500,-275
  rectangle: 0,-275 125,-150
  lines w7: 0,-275 1000,-275 ; 125,-400 125,-150 ; 250,-400 250,-150 ; 500,-400 500,-150 ; 750,-400 750,-150 ; 0,-400 0,-150 1000,-150 1000,-400 0,-400
  text ".Layer_Name" at 577,-858.49 h60
M3 3D STEP Top:
  text ".Layer_Name" at 577,-858.49 h60
M4 3D STEP Bottom:
  text ".Layer_Name" at 577,-858.49 h60
M5 Assembly Top:
  lines w10: -292,-930.17 6308,-930.17 ; -292,-726.83 6310,-726.83 ; -292,-523.5 -292,-1133.5 3713,-1133.5 6310,-1133.5 6310,-523.5 -291.5,-523.5 -291.5,-1133.5 1284,-1133.5 ; 2173,-1133.5 2173,-523.5 ; 3440,-726.83 3440,-523.5 ; 4280,-726.83 4280,-523.5 ; 4902,-1140 4902,-937.17
  text "COMPONENTS MARKED 'DNP' SHOULD NOT BE POPULATED." at 1153.5,-318.5 h60
  text "ASSEMBLY VARIANT:" at 1153,-434 h60
  text ".VariantName" at 2189,-434 h60
  text "PCB VIEWED FROM TOP SIDE" at -228.5,-655.67 h60
  text "BOARD #:" at 2248,-655.67 h60
  text ".PRJ_Number" at 2793.5,-655.67 h60
  text "REV:" at 3638,-655.67 h60
  text ".PCB_Rev" at 3929.5,-655.67 h60
  text "SVN REV:" at 4476,-655.67 h60
  text ".VersionControl_RevNumber" at 4982,-655.67 h60
  text "TID #:" at 2248,-859 h60
  text ".TID" at 2793.5,-859 h60
  text "PLOT NAME =" at -228.5,-1064.34 h60
  text ".plot_File_Name" at 577,-1064.34 h60
  text "GENERATED    :" at 2250,-1064.34 h60
  text ".Print_Date" at 3119.5,-1064.34 h60
  text ".Print_Time" at 3848.5,-1064.34 h60
  text "TEXAS INSTRUMENTS" at 5113,-1064.34 h60
M6 Assembly Bottom:
  lines w10: -292.5,-727.33 6309.5,-727.33 ; -290.5,-930.67 6309.5,-930.67 ; 1115.5,-1140.5 1115.5,-937.67 ; 1737.5,-727.33 1737.5,-524 ; 2577.5,-727.33 2577.5,-524 ; 3844.5,-1134 3844.5,-524 ; 4733.5,-1134 6309,-1134 6309,-524 -292.5,-524 -292.5,-1134 2304.5,-1134 6309.5,-1134 6309.5,-524
  text "COMPONENTS MARKED 'DNP' SHOULD NOT BE POPULATED." at 6102,-318 h60
  text ".VariantName" at 5058,-434 h60
  text "ASSEMBLY VARIANT:" at 6097,-434 h60
  text ".VersionControl_RevNumber" at 1035.5,-656.17 h60
  text "SVN REV:" at 1541.5,-656.17 h60
  text ".PCB_Rev" at 2088,-656.17 h60
  text "REV:" at 2379.5,-656.17 h60
  text ".PRJ_Number" at 3224,-656.17 h60
  text "BOARD #:" at 3769.5,-656.17 h60
  text "PCB VIEWED FROM BOTTOM SIDE" at 6246,-656.17 h60
  text ".TID" at 3224,-859.5 h60
  text "TID #:" at 3769.5,-859.5 h60
  text "TEXAS INSTRUMENTS" at 904.5,-1064.84 h60
  text ".Print_Time" at 2169,-1064.84 h60
  text ".Print_Date" at 2898,-1064.84 h60
  text "GENERATED    :" at 3767.5,-1064.84 h60
  text ".plot_File_Name" at 5440.5,-1064.84 h60
  text "PLOT NAME =" at 6246,-1064.84 h60
M9 Title Sheet:
  drawing of 57 lines, arcs and shapes, not listed
  text "1" at 739.84,8036.5 h70
  text "2" at 3235.5,8036.5 h70
  text "3" at 5724.84,8036.5 h70
  text "4" at 8231.51,8036.5 h70
  text "5" at 10730.5,8036.5 h70
  text "6" at 13235.5,8036.5 h70
  text "A" at -416.5,6893.5 h70
  text "A" at 14383.5,6893.5 h70
  text "B" at -416.5,4513.5 h70
  text "B" at 14383.5,4513.5 h70
  text "C" at -416.5,2138.5 h70
  text "C" at 14383.5,2138.5 h70
  text "PROJECT TITLE:" at 11343.5,277.5 h45
  text ".PRJ_Title" at 11393.5,144.17 h70
  text "DESIGNED FOR:" at 11343.5,-23.5 h45
  text ".PRJ_Customer" at 11393.5,-163.5 h70
  text "D" at -416.5,-231.5 h70
  text "D" at 14383.5,-231.5 h70
  text "FILE NAME:" at 11343.5,-323.5 h45
  text ".PCB_File_Name_No_Path" at 11393.5,-443.5 h70
  text "Texas Instruments (TI) and/or its licensors do not warrant the accuracy or completeness of this specification" at 6374,-605.34 h45
  text "ENGINEER:" at 11343.5,-613.5 h45
  text "LAYOUT BY:" at 12848.5,-613.5 h45
  text "or any information contained therein. TI and/or its licensors do not warrant that this design will meet" at 6329.01,-718 h45
  text ".PRJ_Engineer" at 11393.5,-768.49 h70
  text ".PCB_Layout" at 12899,-768.49 h70
  text "the specifications, will be suitable for your application or fit for any particular purpose, or will operate in" at 6329.01,-830.67 h45
  text ".Layer_Name" at 577,-858.49 h60
  text "ALTIUM DESIGNER VERSION:" at 12848.5,-923.5 h45
  text "an implementation. TI and/or its licensors do not warrant that the design is production worthy. You should" at 6329.01,-943.33 h45
  text "completely validate and test your design implementation to confirm the system functionality for your application." at 6374,-1056 h45
  text ".print_Scale" at 11393.5,-1056.83 h70
  text ".Application_BuildNumber" at 12899,-1056.83 h70
  text "1" at 739.84,-1263.5 h70
  text "2" at 3235.5,-1263.5 h70
  text "3" at 5724.84,-1263.5 h70
  text "4" at 8231.51,-1263.5 h70
  text "5" at 10730.5,-1263.5 h70
  text "6" at 13235.5,-1263.5 h70
M10 Fab Notes:
  drawing of 173 lines, arcs and shapes, not listed
  text "DESIGN INFORMATION" at 12378.02,6201 h60
  text "MIN. TRACK WIDTH:" at 11733.46,6021 h60
  text "10" at 12829.7,6021 h60
  text "MIL" at 12984.46,6021 h60
  text "8" at 12828,5890 h60
  text "MIN. CLEARANCE:" at 11733.46,5889 h60
  text "MIL" at 12984.46,5889 h60
  text "MIN. VIA PAD SIZE:" at 11733.46,5757 h60
  text "24" at 12799.71,5757 h60
  text "MIL" at 12984.46,5757 h60
  text "0.05mm (2MIL)" at 12428.46,5615.29 h60
  text "MINIMUM ANNULAR RING" at 11404.23,5611 h60
  text "EXTERNAL" at 13136.46,5611 h60
  text "PER" at 11604.23,5493 h60
  text "IPC-D-275 CLASS 2 LEVEL C" at 11824.23,5493 h60
  text "MIL, HOLES" at 13312.46,5380.71 h60
  text "+/-" at 12920,5380 h60
  text "+/-" at 13774,5380 h60
  text "REGISTRATION TOLERANCES:" at 11404.23,5375 h60
  text "METAL" at 12604,5375 h60
  text "5" at 13180.2,5375 h60
  text "3" at 14013.2,5375 h60
  text "MIL" at 14129.46,5375 h60
  text "+/-" at 13774,5262 h60
  text "HOLE SIZE TOLERANCE (UNLESS OTHERWISE SPECIFIED):" at 11404.23,5257 h60
  text "3" at 14013.2,5257 h60
  text "MIL" at 14129.46,5257 h60
  text "MATERIAL:" at 11329.46,5047.54 h60
  text "FR-4 High Tg" at 12315.9,4907.21 h60
  text "FR-408" at 11750.46,4898.64 h60
  text "OTHER" at 13238.46,4898.64 h60
  text "X" at 12161,4895 h60
  text "62 MIL (1.6mm) +/-10%" at 12070.56,4735.92 h60
  text "THICKNESS:" at 11404.23,4731.64 h60
  text "X" at 11942.4,4731.64 h60
  text "OTHER" at 13355.46,4731.64 h60
  text "TOLERANCE:" at 11404.23,4573.64 h60
  text "X" at 12243.53,4573.64 h60
  text "ANSI IPC-6012 TYPE 3 CLASS 2" at 12430.48,4573.64 h60
  text "OTHER +/-" at 12430.46,4417.64 h60
  text "BOW & TWIST:" at 11404.23,4260.64 h60
  text "X" at 12243.53,4260.64 h60
  text "ANSI IPC-6012 TYPE 3 CLASS 2" at 12430.48,4260.64 h60
  text "OTHER +/-" at 12430.46,4102.13 h60
  text "DRILLING:" at 11329.46,3963.64 h60
  text "REFERENCE:" at 11404.23,3846.64 h60
  text "X" at 12052.46,3846.64 h60
  text "AS SHOWN" at 12239.46,3846.64 h60
  text "X" at 12953.46,3846.64 h60
  text "NC_DRILL FILES" at 13090.46,3846.64 h60
  text "PTH COPPER THICKNESS:" at 11404.23,3688.64 h60
  text "X" at 12534.46,3688.64 h60
  text "20-30 um" at 12671.46,3688.64 h60
  text "OTHER" at 13388.46,3688.64 h60
  text "BOARD FINISH:" at 11329.46,3529.64 h60
  text "SILKSCREEN:" at 11484.68,3411.64 h60
  text "X" at 12433.46,3411.64 h60
  text "TOP" at 12559.46,3411.64 h60
  text "X" at 12943.46,3411.64 h60
  text "BOTTOM" at 13070.46,3411.64 h60
  text "SILKSCREEN COLOR:" at 11484.68,3244.64 h60
  text "X" at 12432.42,3244.64 h60
  text "WHITE" at 12559.46,3244.64 h60
  text "OTHER" at 13070.46,3244.64 h60
  text "X" at 12563.42,3085.44 h60
  text "GREEN" at 12690.46,3085.44 h60
  text "OTHER" at 13308.46,3085.44 h60
  text "SOLDER RESIST COLOR:" at 11484.68,3074.64 h60
  text "X" at 12563.42,2915.44 h60
  text "MATTE" at 12690.46,2915.44 h60
  text "SEMI-GLOSS" at 13308,2914.8 h60
  text "IMMERSION GOLD (ENIG)" at 12390.46,2726.92 h60
  text "ENEPIG" at 13728,2723.64 h60
  text "SURFACE FINISH:" at 11329.46,2722.64 h60
  text "X" at 12203.51,2722.64 h60
  text "IMM. TIN/SILVER OR EQUIV" at 11659,2565.64 h60
  text "OTHER" at 13090.46,2565.64 h60
  text "ARRAY/PANEL:" at 11329.46,2386.64 h60
  text "CUT AND TRIM PER M1 BOARD OUTLINE" at 12390.46,2382.35 h60
  text "X" at 12205,2236 h60
  text "N.C. ROUTE" at 12390.46,2230.64 h60
  text "V. SCORE" at 13256.46,2230.64 h60
  text "CERTIFICATION:" at 11329.46,2093.64 h60
  text "MATERIALS AND WORKMANSHIP FOR ALL PCBS" at 12054.46,2093.64 h60
  text "TO MEET OR EXCEED THE REQUIREMENTS OF:" at 12054.46,1995.64 h60
  text "X" at 11680.96,1859.13 h60
  text "ANSI IPC-A-600F CLASS ->" at 11819.96,1859.13 h60
  text "X" at 13459.02,1859.13 h60
  text "2" at 13577.96,1859.14 h60
  text "1" at 13262.96,1857.64 h60
  text "3" at 13931.96,1857.64 h60
  text "X" at 12495.02,1699.64 h60
  text "RoHS" at 12631.96,1699.64 h60
  text "OTHER" at 13276.36,1699.64 h60
  text "PER ORDER" at 13673.42,1699.64 h60
  text "ALL BOARDS MUST MEET OR EXCEED UL94-V0 REQUIREMENTS." at 11357,1534 h60
  text "PCB MUST BEAR THE UL94V-0 UL REGISTERED MATERIAL ID NUMBER" at 11357,1414 h60
  text "ADDITIONAL REQUIREMENTS:" at 11329.46,1240.64 h60
  text "MICROSECTION:" at 11404.23,1125.64 h60
  text "YES" at 12309.96,1125.64 h60
  text "REQUIRED" at 13171.46,969.49 h60
  text "BARE BOARD ELEC. TEST:" at 11404.23,966.64 h60
  text "NONE" at 12709.96,966.64 h60
  text "X" at 13044.46,966.64 h60
  text "PER ORDER" at 13763.46,966.64 h60
  text ".Layer_Name" at 577,-858.49 h60
M11 Gerber Information:
  lines w10: -292,-930.17 6308,-930.17 ; -292,-726.83 6310,-726.83 ; -292,-523.5 -292,-1133.5 3713,-1133.5 6310,-1133.5 6310,-523.5 -291.5,-523.5 -291.5,-1133.5 1284,-1133.5 ; 2173,-1133.5 2173,-523.5 ; 3440,-726.83 3440,-523.5 ; 4280,-726.83 4280,-523.5 ; 4902,-1140 4902,-937.17
  text "ALL ARTWORK VIEWED FROM TOP SIDE" at -228.5,-655.67 h60
  text "BOARD #:" at 2248,-655.67 h60
  text ".PRJ_Number" at 2793.5,-655.67 h60
  text "REV:" at 3638,-655.67 h60
  text ".PCB_Rev" at 3929.5,-655.67 h60
  text "SVN REV:" at 4476,-655.67 h60
  text ".VersionControl_RevNumber" at 4982,-655.67 h60
  text "LAYER NAME =" at -228.5,-858.49 h60
  text "TID #:" at 2248,-859 h60
  text ".TID" at 2793.5,-859 h60
  text "PLOT NAME =" at -228.5,-1064.34 h60
  text ".plot_File_Name" at 577,-1064.34 h60
  text "GENERATED    :" at 2250,-1064.34 h60
  text ".Print_Date" at 3119.5,-1064.34 h60
  text ".Print_Time" at 3848.5,-1064.34 h60
  text "TEXAS INSTRUMENTS" at 5113,-1064.34 h60
M12 Stackup:
  drawing of 295 lines, arcs and shapes, not listed
  text "Layer" at 9797.84,7830 h60
  text "Name" at 10207.76,7830 h60
  text "Material" at 11147.5,7830 h60
  text "Thickness" at 12007.26,7830 h60
  text "Constant" at 12657.1,7830 h60
  text "Board Layer Stack" at 13226.96,7830 h60
  text "1" at 9797.84,7710 h60
  text "Top Overlay" at 10207.76,7710 h60
  text "2" at 9797.84,7590 h60
  text "Top Solder" at 10207.76,7590 h60
  text "Solder Resist" at 11147.5,7590 h60
  text "0.40mil" at 12007.26,7590 h60
  text "3.5" at 12657.1,7590 h60
  text "3" at 9797.84,7470 h60
  text "Top Layer" at 10207.76,7470 h60
  text "Copper" at 11147.5,7470 h60
  text "1.40mil" at 12007.26,7470 h60
  text "4" at 9797.84,7350 h60
  text "Dielectric 1" at 10207.76,7350 h60
  text "FR-4" at 11147.5,7350 h60
  text "8.00mil" at 12007.26,7350 h60
  text "4.2" at 12657.1,7350 h60
  text "5" at 9797.84,7230 h60
  text "Signal Layer 1" at 10207.76,7230 h60
  text "Copper" at 11147.5,7230 h60
  text "1.40mil" at 12007.26,7230 h60
  text "6" at 9797.84,7110 h60
  text "Dielectric 2" at 10207.76,7110 h60
  text "FR-4" at 11147.5,7110 h60
  text "8.00mil" at 12007.26,7110 h60
  text "4.2" at 12657.1,7110 h60
  text "7" at 9797.84,6990 h60
  text "Signal Layer 2" at 10207.76,6990 h60
  text "Copper" at 11147.5,6990 h60
  text "1.40mil" at 12007.26,6990 h60
  text "8" at 9797.84,6870 h60
  text "Dielectric 3" at 10207.76,6870 h60
  text "FR-4" at 11147.5,6870 h60
  text "39.60mil" at 12007.26,6870 h60
  text "4.2" at 12657.1,6870 h60
  text "9" at 9797.84,6750 h60
  text "Bottom Layer" at 10207.76,6750 h60
  text "Copper" at 11147.5,6750 h60
  text "1.40mil" at 12007.26,6750 h60
  text "10" at 9797.84,6630 h60
  text "Bottom Solder" at 10207.76,6630 h60
  text "Solder Resist" at 11147.5,6630 h60
  text "0.40mil" at 12007.26,6630 h60
  text "3.5" at 12657.1,6630 h60
  text "11" at 9797.84,6510 h60
  text "Bottom Overlay" at 10207.76,6510 h60
  text ".Layer_Name" at 577,-858.49 h60
M13 Component Bodies Top:
  text ".Layer_Name" at 577,-858.49 h60
M14 Component Bodies Bottom:
  text ".Layer_Name" at 577,-858.49 h60
M15 Courtyards Top:
  text ".Layer_Name" at 577,-858.49 h60
M16 Courtyards Bottom:
  text ".Layer_Name" at 577,-858.49 h60
Drill Drawing:
  circle w10: c5363.72,3017.64 r27.63
  lines w10: 5336.09,2920.95 5391.34,2920.95 5363.72,2865.7 5336.09,2920.95 ; 5336.09,3128.15 5349.9,3128.15 5363.72,3114.34 5377.53,3128.15 5391.34,3128.15 5377.53,3141.96 5391.34,3155.78 5377.53,3155.78 5363.72,3169.59 5349.9,3155.78 5336.09,3155.78 5349.9,3141.96 5336.09,3128.15 ; 5336.09,3238.66 5391.34,3238.66 5391.34,3293.91 5336.09,3293.91 5336.09,3238.66
  lines w12: 5286,2828.4 8517.49,2828.4 ; 5286,3325.68 8517.49,3325.68 ; 5623.86,2704.08 5623.86,3450 ; 5955.86,2704.08 5955.86,3450 ; 6592.43,2704.08 6592.43,3450 ; 6851.57,2704.08 6851.57,3450 ; 7226.72,2704.08 7226.72,3450 ; 7951.05,2704.08 7951.05,3450 ; 5286,2704.08 8517.49,2704.08 8517.49,3450 5286,3450 5286,2704.08
  text "Symbol" at 5360.59,3362.98 h72
  text "Quantity" at 5661.16,3362.98 h72
  text "Finished Hole Size" at 5993.16,3362.98 h72
  text "Plated" at 6629.72,3362.98 h72
  text "Hole Type" at 6888.86,3362.98 h72
  text "Drill Layer Pair" at 7264.02,3362.98 h72
  text "Hole Tolerance" at 7988.35,3362.98 h72
  text "7" at 5661.16,3238.66 h60
  text "7.87mil (0.200mm)" at 5993.16,3238.66 h60
  text "PTH" at 6629.72,3238.66 h60
  text "Round" at 6888.86,3238.66 h60
  text "Top Layer - Bottom Layer" at 7264.02,3238.66 h60
  text "64" at 5661.16,3114.34 h60
  text "8.00mil (0.203mm)" at 5993.16,3114.34 h60
  text "PTH" at 6629.72,3114.34 h60
  text "Round" at 6888.86,3114.34 h60
  text "Top Layer - Bottom Layer" at 7264.02,3114.34 h60
  text "1" at 5661.16,2990.02 h60
  text "41.34mil (1.050mm)" at 5993.16,2990.02 h60
  text "PTH" at 6629.72,2990.02 h60
  text "Round" at 6888.86,2990.02 h60
  text "Top Layer - Bottom Layer" at 7264.02,2990.02 h60
  text "4" at 5661.16,2865.7 h60
  text "61.02mil (1.550mm)" at 5993.16,2865.7 h60
  text "PTH" at 6629.72,2865.7 h60
  text "Round" at 6888.86,2865.7 h60
  text "Top Layer - Bottom Layer" at 7264.02,2865.7 h60
  text "76 Total" at 5661.16,2741.38 h60
  text ".Layer_Name" at 577,-858.49 h60
Mechanical 17:
  region: 957,2017 657,2017 657,1917 957,1917
  text "Note: TI Label and Label Pad / are not being used" at 461,2415.22 h72.83
  text ".Layer_Name" at 577,-858.49 h60
Mechanical 18:
  text ".Layer_Name" at 577,-858.49 h60
Mechanical 19:
  text ".Layer_Name" at 577,-858.49 h60

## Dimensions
78.74,787.4 to 787.4,787.4 on M2 Board Dimensions
787.4,78.74 to 787.4,787.4 on M2 Board Dimensions
0,0 to 0,1043.31 on M2 Board Dimensions
0,0 to 866.14,0 on M2 Board Dimensions
0,-400 to 1000,-400 on M2 Board Dimensions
